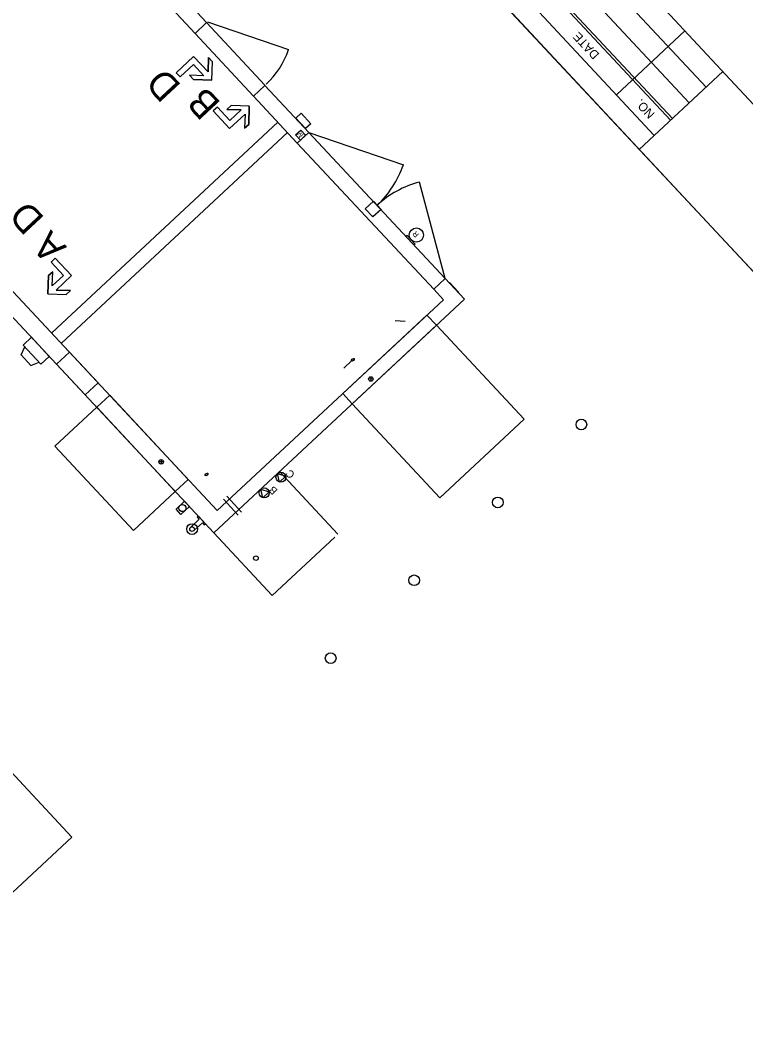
# Model space of a CAD drawing. Extents: x 1121979 to 1130574, y 1838676 to 1848573.
# Drawn here: x 1129644.68 to 1129657.38, y 1839379.61 to 1839397.19 of the extents above; entities that cross this region are included whole.
import ezdxf

# ---------------------------------------------------------------- set-up
doc = ezdxf.new("R2010")
doc.units = 0
for name, color, linetype in [('Default', 7, 'Continuous'), ('Future by Others', 7, 'Continuous'), ('GE-NOT-Notes', 7, 'Continuous'), ('GE-SHT-Clip Border', 7, 'Continuous'), ('GE-SHT-General', 7, 'Continuous'), ('IPDC - EXIST ELECT CONDUIT', 7, 'Continuous'), ('IPDC BUILDING RELATED', 7, 'Continuous'), ('Level 3', 7, 'Continuous'), ('Level 4', 7, 'Continuous'), ('Level 7', 7, 'Continuous'), ('Sheet Text', 7, 'Continuous'), ('Sheets_General Details', 7, 'Continuous')]:
    doc.layers.add(name, color=color, linetype=linetype)

msp = doc.modelspace()

# ---------------------------------------------------------------- linework, layer by layer
at = {"layer": 'Default'}
for p, q in [((1129652.187, 1839392.59), (1129652.193, 1839392.595)), ((1129652.187, 1839392.59), (1129652.347, 1839392.417)), ((1129652.193, 1839392.595), (1129652.351, 1839392.425))]:
    msp.add_line(p, q, dxfattribs=at)
at = {"layer": 'Future by Others'}
for p, q in [((1129650.854, 1839390.903), (1129650.775, 1839390.906)), ((1129650.816, 1839390.944), (1129650.813, 1839390.865)), ((1129647.185, 1839389.452), (1129647.106, 1839389.455)), ((1129647.147, 1839389.493), (1129647.144, 1839389.414))]:
    msp.add_line(p, q, dxfattribs=at)
msp.add_lwpolyline([(1129649.671, 1839395.289), (1129649.5, 1839395.471), (1129649.592, 1839395.557), (1129649.762, 1839395.374)], close=True, dxfattribs=at)
for centre in [(1129650.814, 1839390.905), (1129647.145, 1839389.454)]:
    msp.add_circle(centre, 0.0396, dxfattribs=at)
at = {"layer": 'GE-NOT-Notes'}
for p, q in [((1129647.405, 1839396.266), (1129647.712, 1839396.553)), ((1129647.712, 1839396.553), (1129647.965, 1839396.282)), ((1129647.965, 1839396.282), (1129647.973, 1839396.531)), ((1129648.042, 1839396.458), (1129647.973, 1839396.531)), ((1129648.03, 1839396.138), (1129648.042, 1839396.458)), ((1129647.474, 1839396.193), (1129647.405, 1839396.266)), ((1129647.474, 1839396.193), (1129647.708, 1839396.411)), ((1129647.708, 1839396.411), (1129647.891, 1839396.214)), ((1129647.891, 1839396.214), (1129647.643, 1839396.223)), ((1129647.711, 1839396.15), (1129647.643, 1839396.223)), ((1129648.03, 1839396.138), (1129647.711, 1839396.15)), ((1129648.128, 1839395.666), (1129648.055, 1839395.598)), ((1129648.055, 1839395.598), (1129648.341, 1839395.291)), ((1129648.128, 1839395.666), (1129648.346, 1839395.432)), ((1129648.368, 1839395.693), (1129648.295, 1839395.625)), ((1129648.544, 1839395.616), (1129648.295, 1839395.625)), ((1129648.341, 1839395.291), (1129648.612, 1839395.543)), ((1129648.346, 1839395.432), (1129648.544, 1839395.616)), ((1129648.687, 1839395.682), (1129648.368, 1839395.693)), ((1129648.612, 1839395.543), (1129648.603, 1839395.294)), ((1129648.687, 1839395.682), (1129648.676, 1839395.362)), ((1129648.676, 1839395.362), (1129648.603, 1839395.294)), ((1129645.218, 1839392.952), (1129645.291, 1839393.021)), ((1129645.218, 1839392.952), (1129645.436, 1839392.718)), ((1129645.291, 1839393.021), (1129645.577, 1839392.714)), ((1129645.174, 1839392.715), (1129645.247, 1839392.783)), ((1129645.239, 1839392.534), (1129645.247, 1839392.783)), ((1129645.163, 1839392.396), (1129645.174, 1839392.715)), ((1129645.436, 1839392.718), (1129645.239, 1839392.534)), ((1129645.577, 1839392.714), (1129645.307, 1839392.461)), ((1129645.163, 1839392.396), (1129645.483, 1839392.384)), ((1129645.307, 1839392.461), (1129645.556, 1839392.453)), ((1129645.483, 1839392.384), (1129645.556, 1839392.453))]:
    msp.add_line(p, q, dxfattribs=at)
at = {"layer": 'GE-SHT-Clip Border'}
msp.add_lwpolyline([(1129652.729, 1839339.252), (1129609.766, 1839385.33), (1129639.021, 1839412.608), (1129681.985, 1839366.531)], close=True, dxfattribs=at)
msp.add_lwpolyline([(1129652.729, 1839339.252), (1129609.766, 1839385.33), (1129639.021, 1839412.608), (1129681.985, 1839366.531)], close=True, dxfattribs=at)
msp.add_lwpolyline([(1129652.729, 1839339.252), (1129609.766, 1839385.33), (1129639.021, 1839412.608), (1129681.985, 1839366.531)], close=True, dxfattribs=at)
at = {"layer": 'GE-SHT-General'}
for p, q in [((1129656.061, 1839395.434), (1129639.57, 1839413.12)), ((1129656.092, 1839395.463), (1129639.601, 1839413.149)), ((1129639.021, 1839412.608), (1129681.985, 1839366.531)), ((1129656.682, 1839396.013), (1129650.544, 1839402.596)), ((1129656.387, 1839395.738), (1129650.249, 1839402.321)), ((1129649.638, 1839401.75), (1129655.775, 1839395.168)), ((1129656.311, 1839396.998), (1129655.112, 1839395.88)), ((1129656.975, 1839396.286), (1129655.512, 1839394.922)), ((1129656.975, 1839396.286), (1129655.512, 1839394.922))]:
    msp.add_line(p, q, dxfattribs=at)
msp.add_lwpolyline([(1129652.729, 1839339.252), (1129609.766, 1839385.33), (1129640.484, 1839413.972), (1129683.448, 1839367.895)], close=True, dxfattribs=at)
at = {"layer": 'IPDC - EXIST ELECT CONDUIT'}
msp.add_line((1129650.478, 1839391.221), (1129650.341, 1839391.093), dxfattribs=at)
for centre, major_axis in [((1129650.5, 1839391.242), (-0.0221, -0.0206)), ((1129647.939, 1839389.234), (0.0221, 0.0206))]:
    msp.add_ellipse(centre, major_axis=major_axis, ratio=0.534795, dxfattribs=at)
at = {"layer": 'IPDC BUILDING RELATED'}
for p, q in [((1129648.96, 1839396.047), (1129647.94, 1839397.144)), ((1129648.76, 1839395.858), (1129647.737, 1839396.955)), ((1129649.728, 1839395.223), (1129651.383, 1839394.654)), ((1129652.115, 1839392.663), (1129649.728, 1839395.222)), ((1129651.914, 1839392.475), (1129649.527, 1839395.035)), ((1129652.115, 1839392.663), (1129651.663, 1839394.353)), ((1129651.449, 1839393.418), (1129651.427, 1839393.4)), ((1129651.592, 1839393.264), (1129651.449, 1839393.418)), ((1129651.572, 1839393.245), (1129651.592, 1839393.264)), ((1129651.963, 1839391.845), (1129653.497, 1839390.2)), ((1129638.197, 1839390.802), (1129645.58, 1839382.884)), ((1129650.489, 1839390.471), (1129652.024, 1839388.825)), ((1129646.017, 1839390.409), (1129645.286, 1839389.727)), ((1129653.497, 1839390.2), (1129652.024, 1839388.825)), ((1129646.66, 1839388.253), (1129645.286, 1839389.727)), ((1129647.391, 1839388.935), (1129646.66, 1839388.253)), ((1129647.657, 1839388.305), (1129647.809, 1839388.447)), ((1129647.713, 1839388.246), (1129647.865, 1839388.388)), ((1129647.776, 1839388.483), (1129647.796, 1839388.501)), ((1129647.809, 1839388.447), (1129647.776, 1839388.483)), ((1129647.776, 1839388.483), (1129647.776, 1839388.483)), ((1129647.918, 1839388.37), (1129647.796, 1839388.501)), ((1129647.865, 1839388.388), (1129647.898, 1839388.352)), ((1129647.898, 1839388.352), (1129647.918, 1839388.37)), ((1129647.898, 1839388.352), (1129647.898, 1839388.352)), ((1129638.997, 1839376.747), (1129645.58, 1839382.884))]:
    msp.add_line(p, q, dxfattribs=at)
for points in [[(1129639.497, 1839406.199), (1129647.94, 1839397.144)], [(1129647.737, 1839396.955), (1129639.507, 1839405.781)], [(1129635.108, 1839402.107), (1129648.066, 1839388.211), (1129652.454, 1839392.303), (1129652.117, 1839392.664)], [(1129652.084, 1839392.292), (1129648.126, 1839388.601), (1129635.548, 1839402.09)]]:
    msp.add_lwpolyline(points, dxfattribs=at)
for points in [[(1129650.849, 1839393.742), (1129650.716, 1839393.885), (1129650.859, 1839394.018), (1129650.992, 1839393.875)], [(1129649.182, 1839389.247), (1129649.326, 1839389.203), (1129649.216, 1839389.1)], [(1129648.888, 1839388.973), (1129649.032, 1839388.929), (1129648.922, 1839388.826)], [(1129647.491, 1839388.532), (1129647.404, 1839388.626), (1129647.551, 1839388.764), (1129647.638, 1839388.67)]]:
    msp.add_lwpolyline(points, close=True, dxfattribs=at)
for centre, radius in [((1129651.611, 1839393.425), 0.124), ((1129649.241, 1839389.184), 0.0871), ((1129648.948, 1839388.91), 0.0871), ((1129647.516, 1839388.644), 0.0625), ((1129647.685, 1839388.276), 0.0938), ((1129647.685, 1839388.276), 0.0406)]:
    msp.add_circle(centre, radius, dxfattribs=at)
for centre, start, end in [((1129649.728, 1839395.223), 313.0219, 341.0169), ((1129652.115, 1839392.663), 104.9774, 132.9724)]:
    msp.add_arc(centre, 1.75, start, end, dxfattribs=at)
at = {"layer": 'Level 3'}
msp.add_line((1129651.413, 1839391.911), (1129651.238, 1839391.922), dxfattribs=at)
for points in [[(1129649.582, 1839395.086), (1129649.496, 1839395.177), (1129649.588, 1839395.263), (1129649.673, 1839395.171)], [(1129650.489, 1839390.471), (1129651.963, 1839391.845), (1129651.796, 1839392.024), (1129650.323, 1839390.65)], [(1129645.314, 1839391.163), (1129645.814, 1839390.627), (1129646.04, 1839390.838), (1129645.54, 1839391.375)], [(1129646.04, 1839390.838), (1129645.54, 1839391.374), (1129645.314, 1839391.163), (1129645.814, 1839390.627)], [(1129646.017, 1839390.409), (1129647.391, 1839388.935), (1129647.618, 1839389.147), (1129646.244, 1839390.62)]]:
    msp.add_lwpolyline(points, close=True, dxfattribs=at)
at = {"layer": 'Level 7'}
for p, q in [((1129647.956, 1839397.161), (1129649.371, 1839396.675)), ((1129648.961, 1839396.046), (1129648.76, 1839395.858)), ((1129649.728, 1839395.222), (1129649.527, 1839395.035)), ((1129652.117, 1839392.664), (1129651.914, 1839392.475))]:
    msp.add_line(p, q, dxfattribs=at)
for points in [[(1129647.737, 1839396.955), (1129647.94, 1839397.144)], [(1129648.961, 1839396.045), (1129649.728, 1839395.222)], [(1129649.527, 1839395.035), (1129648.76, 1839395.858)], [(1129645.23, 1839391.712), (1129649.186, 1839395.401)], [(1129645.4, 1839391.529), (1129649.356, 1839395.218)], [(1129652.084, 1839392.292), (1129651.914, 1839392.475)]]:
    msp.add_lwpolyline(points, dxfattribs=at)
for centre in [(1129654.499, 1839390.107), (1129653.036, 1839388.743), (1129651.573, 1839387.379), (1129650.111, 1839386.015)]:
    msp.add_circle(centre, 0.0938, dxfattribs=at)
msp.add_arc((1129647.959, 1839397.159), 1.497, 312.9971, 341.0169, dxfattribs=at)
at = {"layer": 'Sheet Text'}
for p, q in [((1129649.214, 1839389.282), (1129650.237, 1839388.185)), ((1129648.066, 1839388.211), (1129649.089, 1839387.114)), ((1129649.089, 1839387.114), (1129650.186, 1839388.137))]:
    msp.add_line(p, q, dxfattribs=at)
at = {"layer": 'Sheets_General Details'}
for p, q in [((1129647.712, 1839396.553), (1129647.405, 1839396.266)), ((1129647.712, 1839396.553), (1129647.405, 1839396.266)), ((1129647.965, 1839396.282), (1129647.712, 1839396.553)), ((1129647.965, 1839396.282), (1129647.712, 1839396.553)), ((1129647.973, 1839396.531), (1129647.965, 1839396.282)), ((1129647.973, 1839396.531), (1129647.965, 1839396.282)), ((1129648.042, 1839396.458), (1129647.973, 1839396.531)), ((1129648.042, 1839396.458), (1129647.973, 1839396.531)), ((1129648.03, 1839396.138), (1129648.042, 1839396.458)), ((1129648.03, 1839396.138), (1129648.042, 1839396.458)), ((1129647.405, 1839396.266), (1129647.474, 1839396.193)), ((1129647.405, 1839396.266), (1129647.474, 1839396.193)), ((1129647.474, 1839396.193), (1129647.708, 1839396.411)), ((1129647.474, 1839396.193), (1129647.708, 1839396.411)), ((1129647.708, 1839396.411), (1129647.891, 1839396.214)), ((1129647.708, 1839396.411), (1129647.891, 1839396.214)), ((1129647.891, 1839396.214), (1129647.643, 1839396.223)), ((1129647.643, 1839396.223), (1129647.711, 1839396.15)), ((1129647.891, 1839396.214), (1129647.643, 1839396.223)), ((1129647.643, 1839396.223), (1129647.711, 1839396.15)), ((1129647.711, 1839396.15), (1129648.03, 1839396.138)), ((1129647.711, 1839396.15), (1129648.03, 1839396.138)), ((1129648.128, 1839395.666), (1129648.055, 1839395.598)), ((1129648.128, 1839395.666), (1129648.055, 1839395.598)), ((1129648.055, 1839395.598), (1129648.341, 1839395.291)), ((1129648.055, 1839395.598), (1129648.341, 1839395.291)), ((1129648.346, 1839395.432), (1129648.128, 1839395.666)), ((1129648.346, 1839395.432), (1129648.128, 1839395.666)), ((1129648.368, 1839395.693), (1129648.295, 1839395.625)), ((1129648.368, 1839395.693), (1129648.295, 1839395.625)), ((1129648.295, 1839395.625), (1129648.544, 1839395.616)), ((1129648.295, 1839395.625), (1129648.544, 1839395.616)), ((1129648.341, 1839395.291), (1129648.612, 1839395.543)), ((1129648.341, 1839395.291), (1129648.612, 1839395.543)), ((1129648.544, 1839395.616), (1129648.346, 1839395.432)), ((1129648.544, 1839395.616), (1129648.346, 1839395.432)), ((1129648.687, 1839395.682), (1129648.368, 1839395.693)), ((1129648.687, 1839395.682), (1129648.368, 1839395.693)), ((1129648.612, 1839395.543), (1129648.603, 1839395.294)), ((1129648.612, 1839395.543), (1129648.603, 1839395.294)), ((1129648.676, 1839395.362), (1129648.687, 1839395.682)), ((1129648.676, 1839395.362), (1129648.687, 1839395.682)), ((1129648.603, 1839395.294), (1129648.676, 1839395.362)), ((1129648.603, 1839395.294), (1129648.676, 1839395.362)), ((1129645.291, 1839393.021), (1129645.218, 1839392.952)), ((1129645.218, 1839392.952), (1129645.436, 1839392.718)), ((1129645.577, 1839392.714), (1129645.291, 1839393.021)), ((1129645.247, 1839392.783), (1129645.174, 1839392.715)), ((1129645.239, 1839392.534), (1129645.247, 1839392.783)), ((1129645.174, 1839392.715), (1129645.163, 1839392.396)), ((1129645.436, 1839392.718), (1129645.239, 1839392.534)), ((1129645.307, 1839392.461), (1129645.577, 1839392.714)), ((1129645.163, 1839392.396), (1129645.483, 1839392.384)), ((1129645.556, 1839392.453), (1129645.307, 1839392.461)), ((1129645.483, 1839392.384), (1129645.556, 1839392.453)), ((1129644.728, 1839391.498), (1129644.874, 1839391.635)), ((1129645.039, 1839391.164), (1129644.728, 1839391.498)), ((1129645.186, 1839391.3), (1129644.874, 1839391.635)), ((1129644.693, 1839391.325), (1129644.759, 1839391.465)), ((1129644.864, 1839391.142), (1129644.693, 1839391.325)), ((1129644.864, 1839391.142), (1129645.008, 1839391.198)), ((1129645.039, 1839391.164), (1129645.186, 1839391.3)), ((1129648.494, 1839388.519), (1129648.234, 1839388.798)), ((1129648.292, 1839388.853), (1129648.553, 1839388.574))]:
    msp.add_line(p, q, dxfattribs=at)
msp.add_circle((1129648.803, 1839387.767), 0.0399, dxfattribs=at)

# ---------------------------------------------------------------- texts
at = {"layer": 'GE-NOT-Notes'}
for s, p in [('D', (1129647.511, 1839396.042)), ('B', (1129648.204, 1839395.733)), ('D', (1129645.118, 1839393.72)), ('A', (1129645.502, 1839393.214))]:
    msp.add_text(s, height=0.48, rotation=132.9971, dxfattribs=at).set_placement(p)
at = {"layer": 'GE-SHT-General'}
for s, p in [('DATE', (1129654.824, 1839396.592)), ('NO.', (1129655.794, 1839395.551))]:
    msp.add_text(s, height=0.154, rotation=132.9972, dxfattribs=at).set_placement(p)
at = {"layer": 'IPDC BUILDING RELATED'}
for s, height, p in [('R', 0.0944, (1129651.665, 1839393.436)), ('C', 0.133, (1129649.494, 1839389.236)), ('B', 0.133, (1129649.192, 1839388.954))]:
    msp.add_text(s, height=height, rotation=132.9971, dxfattribs=at).set_placement(p)
at = {"layer": 'Level 4'}
msp.add_text('M', height=0.0944, rotation=132.9971, dxfattribs=at).set_placement((1129649.641, 1839395.179))

doc.saveas('drawing.dxf')
